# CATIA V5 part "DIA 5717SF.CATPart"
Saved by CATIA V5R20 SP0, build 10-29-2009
Part number: DIA 5717SF
Revision: ANY
Definition: UNKNOWN
Nomenclature: DIA 5717SF
Source: Unknown
Bounding box of the stored display mesh (mm): x -2.85 to 2.85, y -7.925 to 9.045, z -2.711 to 2.711
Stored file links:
  C:\Users\Utente\Desktop\IO LAVORO\3D X SITO CF\CUMSA\3D files FA\FA 105706-21\DIA 5717SF.CATPart
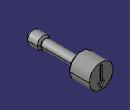
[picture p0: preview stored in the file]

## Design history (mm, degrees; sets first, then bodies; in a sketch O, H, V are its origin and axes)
Body1 "Cortar-Extruir2" (main body)
  Solid1: solid without history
